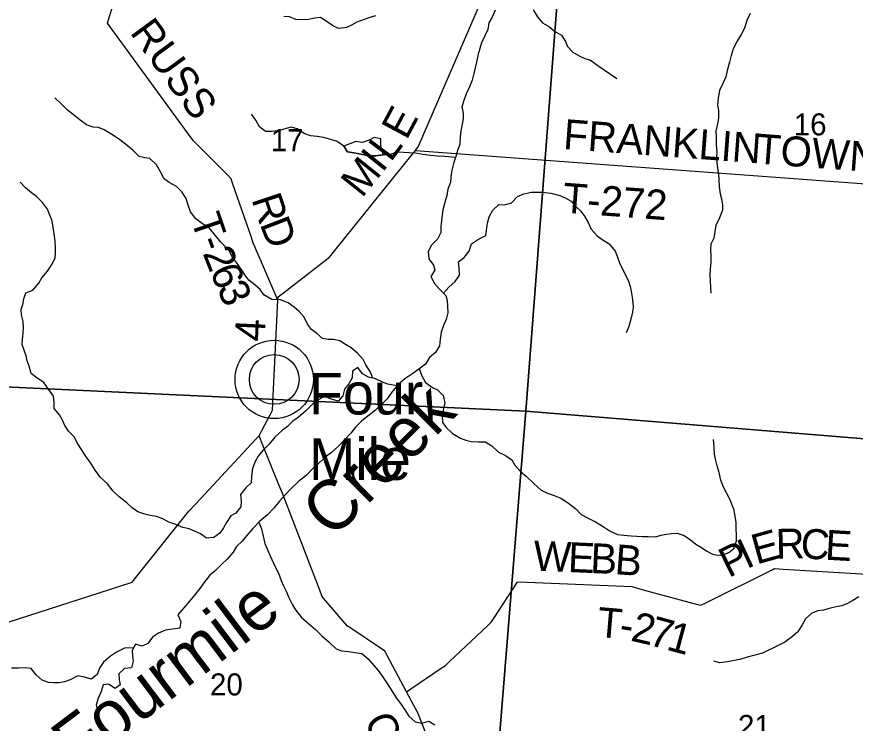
# Model space of a CAD drawing. Extents: x 0 to 42, y 0 to 22.
# Drawn here: x 2.716 to 3.512, y 17.925 to 18.596 of the extents above; entities that cross this region are included whole.
import ezdxf

# ---------------------------------------------------------------- set-up
doc = ezdxf.new("R2010")
doc.units = 0
for name, color, linetype in [('GM_X_County_Road', 7, 'Continuous'), ('GM_X_County_Road_Text', 7, 'Continuous'), ('GM_X_Minor_Lake', 7, 'Continuous'), ('GM_X_Minor_River', 7, 'Continuous'), ('GM_X_Minor_River_Text', 7, 'Continuous'), ('GM_X_Section', 7, 'Continuous'), ('GM_X_Section_Text', 7, 'Continuous'), ('GM_X_Township_Road', 7, 'Continuous'), ('GM_X_Township_Road_Text', 7, 'Continuous'), ('GM_X_Unincorporated', 7, 'Continuous'), ('GM_X_Unincorporated_Location', 7, 'Continuous'), ('GM_X_Unincorporated_Text', 7, 'Continuous')]:
    doc.layers.add(name, color=color, linetype=linetype)

msp = doc.modelspace()

# ---------------------------------------------------------------- linework, layer by layer
at = {"layer": 'GM_X_County_Road'}
for points in [[(2.94626, 18.1983), (2.94861, 18.20278), (2.95764, 18.22006), (2.95897, 18.22261), (2.95931, 18.22947), (2.96412, 18.32681), (2.96428, 18.3301), (2.96939, 18.33404), (3.01182, 18.36678), (3.01303, 18.3677), (3.01819, 18.3741), (3.09159, 18.46515), (3.09478, 18.46912), (3.0976, 18.47306), (3.21925, 18.75503)], [(2.48506, 17.97141), (2.49188, 17.97404), (2.50643, 17.97938), (2.51843, 17.98366), (2.54665, 17.99534), (2.55686, 17.99531), (2.63519, 17.99232), (2.6369, 17.99225), (2.6435, 17.99691), (2.6515, 18.00257), (2.65302, 18.00364), (2.66057, 18.00607), (2.67923, 18.01208), (2.8238, 18.05864), (2.82582, 18.05928), (2.83058, 18.06526), (2.87941, 18.12659), (2.88608, 18.13376), (2.94289, 18.19468), (2.94626, 18.1983)], [(3.11725, 17.88388), (3.09745, 17.93368), (3.0963, 17.93658), (3.09317, 17.94242), (3.08627, 17.95531), (3.06787, 17.98968), (3.06557, 17.99394), (3.06151, 17.99668), (3.03322, 18.01571), (3.03029, 18.01768), (3.0262, 18.02237), (3.00697, 18.0444), (3.00658, 18.04484), (3.00328, 18.05338), (2.96813, 18.14428), (2.96446, 18.1533), (2.94985, 18.18944), (2.94626, 18.1983)]]:
    msp.add_lwpolyline(points, dxfattribs=at)
at = {"layer": 'GM_X_Minor_Lake'}
for points in [[(3.06396, 18.46475), (3.06191, 18.47385), (3.06174, 18.47992), (3.05551, 18.48146), (3.05058, 18.47864), (3.04452, 18.47658), (3.03809, 18.47755), (3.02673, 18.47323)], [(3.02673, 18.47323), (3.03011, 18.46772), (3.03616, 18.46675), (3.04315, 18.46559), (3.04996, 18.46405), (3.05715, 18.46402), (3.06396, 18.46475)]]:
    msp.add_lwpolyline(points, dxfattribs=at)
at = {"layer": 'GM_X_Minor_River'}
for points in [[(3.17039, 18.60213), (3.16753, 18.59551), (3.16448, 18.59003), (3.16332, 18.58378), (3.16046, 18.57772), (3.15741, 18.5711), (3.15569, 18.5658), (3.15416, 18.56031), (3.15262, 18.55292), (3.15146, 18.54743), (3.15012, 18.54213), (3.14839, 18.53588), (3.14591, 18.52926), (3.14286, 18.52263), (3.14057, 18.51658), (3.13884, 18.51052), (3.13995, 18.50426), (3.13994, 18.49933), (3.13897, 18.49403), (3.13762, 18.48778), (3.13722, 18.4821), (3.13682, 18.47508), (3.13453, 18.46884), (3.13299, 18.46316), (3.1307, 18.45672), (3.12916, 18.45047), (3.12838, 18.44403), (3.1278, 18.43873), (3.1255, 18.43229), (3.12453, 18.42623), (3.12262, 18.41979), (3.1207, 18.41279), (3.12012, 18.40805), (3.11953, 18.40218), (3.11875, 18.39725), (3.11873, 18.39119), (3.11549, 18.38495), (3.1096, 18.3789), (3.10675, 18.37285), (3.10748, 18.36621), (3.11181, 18.36032), (3.11311, 18.35558), (3.10931, 18.34934), (3.11269, 18.34269), (3.11759, 18.33736), (3.12343, 18.33147), (3.12492, 18.32653), (3.12509, 18.32123), (3.12526, 18.31478), (3.12391, 18.30853), (3.12124, 18.30286), (3.11914, 18.29661), (3.11798, 18.28998), (3.11739, 18.28373), (3.11377, 18.2773), (3.10789, 18.27239), (3.10408, 18.26615), (3.09782, 18.26163), (3.09213, 18.25748)], [(3.20633, 18.60237), (3.21047, 18.59572), (3.21518, 18.59002), (3.22178, 18.5862), (3.22668, 18.58221), (3.23329, 18.57839), (3.23705, 18.57231), (3.23893, 18.56756), (3.24401, 18.56224), (3.25062, 18.55842), (3.25553, 18.55632), (3.26082, 18.55478), (3.2678, 18.54964), (3.28591, 18.53744)], [(3.05669, 18.59688), (3.05139, 18.5952), (3.04609, 18.59332), (3.03908, 18.5907), (3.03396, 18.58787), (3.02922, 18.58562), (3.02203, 18.5847), (3.01674, 18.58699), (3.0109, 18.59118), (3.00467, 18.59519), (2.99918, 18.59464), (2.99312, 18.59334), (2.98783, 18.59298), (2.98121, 18.59338), (2.97497, 18.59587), (2.96987, 18.59608)], [(3.4123, 18.59912), (3.40925, 18.59231), (3.40696, 18.58512), (3.40391, 18.57906), (3.39991, 18.57263), (3.39629, 18.56544), (3.39438, 18.55901), (3.39284, 18.55295), (3.39054, 18.54481), (3.38919, 18.53894), (3.38652, 18.53269), (3.38328, 18.52588), (3.38193, 18.51887), (3.38153, 18.51205), (3.38227, 18.50693), (3.38224, 18.49973), (3.38127, 18.49424), (3.37993, 18.48723), (3.38009, 18.48192), (3.38026, 18.47434), (3.38061, 18.46751), (3.3804, 18.4624), (3.38076, 18.45766), (3.3815, 18.45235), (3.38223, 18.44609), (3.38259, 18.44135), (3.38294, 18.43453), (3.38406, 18.42789), (3.38517, 18.42314), (3.3861, 18.41708), (3.38608, 18.41234), (3.38321, 18.40496), (3.37997, 18.39777), (3.37882, 18.39171), (3.37804, 18.38583), (3.37518, 18.37997), (3.37478, 18.37523), (3.37514, 18.36822), (3.37512, 18.36348), (3.37452, 18.35647), (3.37413, 18.35135), (3.37429, 18.3451), (3.37465, 18.33941), (3.3752, 18.33353)], [(3.05412, 18.25298), (3.05204, 18.25877), (3.04752, 18.26561), (3.04489, 18.27074), (3.03962, 18.27663), (3.03377, 18.28177), (3.0283, 18.28502), (3.02302, 18.28845), (3.01697, 18.28961), (3.01167, 18.28963), (3.00657, 18.2906), (3.00091, 18.29517), (2.99601, 18.29917), (2.99224, 18.30411), (2.98905, 18.31075), (2.98434, 18.31627), (2.97944, 18.32046), (2.97378, 18.32446), (2.96642, 18.32714), (2.95828, 18.32774), (2.95073, 18.33213), (2.94716, 18.33707), (2.94226, 18.34164), (2.93641, 18.34602), (2.93283, 18.35096), (2.92907, 18.35647), (2.92493, 18.36274), (2.92098, 18.36788), (2.91741, 18.37433), (2.91006, 18.38194), (2.90441, 18.3886), (2.89876, 18.39544), (2.89253, 18.39945), (2.88631, 18.40402), (2.88104, 18.41087), (2.87861, 18.41808), (2.87692, 18.42358), (2.87298, 18.42985), (2.8677, 18.4348), (2.8609, 18.43862), (2.856, 18.44205), (2.85262, 18.44888), (2.84886, 18.45534), (2.84264, 18.46143), (2.83772, 18.46202), (2.83243, 18.46317), (2.82659, 18.46888), (2.82093, 18.47383), (2.81414, 18.47917), (2.80886, 18.4826), (2.80395, 18.48565), (2.79905, 18.48851), (2.79376, 18.4908), (2.78884, 18.4912), (2.78242, 18.49331), (2.77638, 18.49788), (2.76959, 18.50322), (2.76431, 18.50741), (2.75828, 18.51331), (2.75225, 18.51883)], [(3.13274, 18.46245), (3.1224, 18.4632), (3.11559, 18.4636), (3.10898, 18.46439), (3.1016, 18.46517), (3.09461, 18.46634), (3.08837, 18.46674), (3.08345, 18.46695), (3.07683, 18.46735), (3.07001, 18.46473), (3.06396, 18.46475), (3.05715, 18.46402), (3.04996, 18.46405), (3.04315, 18.46559), (3.03616, 18.46675), (3.03011, 18.46772), (3.02673, 18.47323), (3.0205, 18.47762), (3.01351, 18.47973), (3.00746, 18.48127), (3.00123, 18.48224), (2.99517, 18.48283), (2.9897, 18.48475), (2.98253, 18.4897), (2.97686, 18.49105), (2.97193, 18.48993), (2.96569, 18.48806), (2.95868, 18.48695), (2.95225, 18.48716), (2.94678, 18.49135), (2.94302, 18.49781), (2.93907, 18.50351)], [(2.74955, 18.40322), (2.7473, 18.40835), (2.74543, 18.41328), (2.74072, 18.41974), (2.73507, 18.42526), (2.73016, 18.42869), (2.72451, 18.43364), (2.71942, 18.43878)], [(3.12135, 18.33356), (3.12648, 18.33942), (3.13237, 18.34451), (3.13636, 18.35056), (3.13619, 18.35719), (3.13565, 18.36345), (3.14077, 18.36741), (3.14571, 18.37346), (3.14801, 18.38046), (3.15446, 18.38499), (3.16147, 18.38837), (3.16224, 18.39311), (3.16302, 18.39993), (3.16456, 18.40599), (3.16818, 18.41242), (3.17387, 18.41789), (3.17917, 18.4173), (3.18579, 18.41917), (3.19149, 18.42522), (3.19755, 18.42785), (3.20475, 18.42952), (3.20966, 18.42932), (3.21477, 18.4293), (3.22328, 18.42851), (3.23178, 18.42639), (3.23669, 18.42391), (3.24236, 18.42085), (3.24669, 18.4161), (3.25159, 18.41134), (3.25517, 18.40659), (3.25855, 18.4007), (3.26155, 18.39424), (3.26701, 18.38797), (3.27192, 18.38454), (3.27871, 18.38034), (3.28417, 18.3735), (3.28605, 18.36875), (3.28848, 18.3623), (3.29167, 18.35565), (3.29411, 18.3509), (3.29693, 18.34483), (3.29861, 18.33989), (3.29991, 18.33344), (3.30084, 18.32737), (3.30119, 18.32055), (3.30079, 18.31562), (3.29925, 18.30881), (3.29715, 18.30199), (3.29467, 18.29594)], [(3.07713, 18.24575), (3.06845, 18.24715), (3.06354, 18.24906), (3.05674, 18.25231), (3.04994, 18.25404), (3.04428, 18.2569), (3.03995, 18.26299), (3.03502, 18.25959), (3.03461, 18.25315), (3.03138, 18.24767), (3.02739, 18.24237), (3.02566, 18.23613), (3.02129, 18.23122), (3.01487, 18.23295), (3.00845, 18.23544), (3.00219, 18.23224), (2.9965, 18.2279), (2.99024, 18.22148), (2.98322, 18.21563), (2.97828, 18.21205), (2.97335, 18.20714), (2.96823, 18.20318), (2.96121, 18.19695), (2.95588, 18.19015), (2.94981, 18.1843), (2.94544, 18.17882), (2.94239, 18.1739), (2.93991, 18.16728), (2.93913, 18.15989), (2.93873, 18.15363), (2.9336, 18.14873), (2.92866, 18.14268), (2.9292, 18.13623), (2.92881, 18.13093), (2.92424, 18.12469), (2.91932, 18.12225), (2.91532, 18.11601), (2.91246, 18.1109), (2.90904, 18.10598), (2.90316, 18.10184), (2.89616, 18.10111), (2.8905, 18.10511), (2.88484, 18.10778), (2.87974, 18.11008), (2.87388, 18.11124), (2.86727, 18.11392), (2.86047, 18.11622), (2.8548, 18.11946), (2.84895, 18.12157), (2.8429, 18.12273), (2.8378, 18.12389), (2.83119, 18.12618), (2.82571, 18.13), (2.82081, 18.13456), (2.81327, 18.14028), (2.80761, 18.1458), (2.80234, 18.15264), (2.79556, 18.15854), (2.79047, 18.16557), (2.78577, 18.17317), (2.7822, 18.17831), (2.7775, 18.18534), (2.7743, 18.19066), (2.77054, 18.19711), (2.76527, 18.20263), (2.76188, 18.20814), (2.75963, 18.21308), (2.75662, 18.21802), (2.75173, 18.2241), (2.75156, 18.22979), (2.7512, 18.23585), (2.74631, 18.24251), (2.74198, 18.24897), (2.73556, 18.25278), (2.72972, 18.25735), (2.72785, 18.26437), (2.72617, 18.2695), (2.72524, 18.27424), (2.72337, 18.27936), (2.72131, 18.28449), (2.72151, 18.28961), (2.72229, 18.29548), (2.72269, 18.30059), (2.72214, 18.30666), (2.72066, 18.31311), (2.72048, 18.31804), (2.72202, 18.32296), (2.72298, 18.32827), (2.7247, 18.33394), (2.73133, 18.33657), (2.73722, 18.34318), (2.74008, 18.3481), (2.7454, 18.35452), (2.75015, 18.3619), (2.75263, 18.3672), (2.75303, 18.37193), (2.75305, 18.37667), (2.75269, 18.38293), (2.75195, 18.38767), (2.75048, 18.39829), (2.74955, 18.40322)], [(3.09833, 18.26199), (3.10064, 18.25517), (3.10421, 18.24871), (3.11081, 18.24395), (3.11572, 18.24185), (3.121, 18.23633), (3.12248, 18.2295), (3.12094, 18.22249), (3.12017, 18.21738), (3.12033, 18.21093), (3.12372, 18.20618), (3.12994, 18.20047), (3.1373, 18.1959), (3.1424, 18.19398), (3.14769, 18.19282), (3.15412, 18.19242), (3.16075, 18.19258), (3.16716, 18.18877), (3.17338, 18.18268), (3.17999, 18.17962), (3.18603, 18.17543), (3.18903, 18.17049), (3.1945, 18.16421), (3.19978, 18.15983), (3.20751, 18.1526), (3.2141, 18.14651), (3.22015, 18.14383), (3.22619, 18.14154), (3.2328, 18.13905), (3.23997, 18.13428), (3.24676, 18.12895), (3.25185, 18.12362), (3.25751, 18.12057), (3.26563, 18.11656), (3.2728, 18.11217), (3.27941, 18.1076), (3.28658, 18.10473), (3.29263, 18.10394), (3.29944, 18.10316), (3.30474, 18.10295), (3.30984, 18.10274), (3.31552, 18.10253), (3.32289, 18.10231), (3.32763, 18.104), (3.33293, 18.10493), (3.33785, 18.10548), (3.34296, 18.10583), (3.34976, 18.10353), (3.35579, 18.09953), (3.36089, 18.09553), (3.36617, 18.0921), (3.37126, 18.08867), (3.37655, 18.08599), (3.38147, 18.08503), (3.38657, 18.0852), (3.39226, 18.08745), (3.397, 18.09141), (3.39948, 18.09842), (3.39931, 18.10315), (3.39915, 18.1113), (3.39898, 18.11642), (3.39825, 18.12173), (3.39732, 18.1278), (3.39395, 18.13578), (3.39151, 18.14128), (3.38869, 18.14622), (3.38644, 18.15116), (3.38457, 18.15628), (3.38289, 18.1633), (3.38121, 18.16975), (3.37953, 18.17601), (3.3786, 18.18094), (3.37825, 18.18739), (3.37752, 18.19459)], [(3.09213, 18.25748), (3.08474, 18.25239), (3.07791, 18.24673), (3.0724, 18.23974), (3.06783, 18.23331), (3.06176, 18.22727), (3.05663, 18.22255), (3.04961, 18.21689), (3.04373, 18.21255), (3.03785, 18.20651), (3.03329, 18.20065), (3.02759, 18.1948), (3.02208, 18.18857), (3.01506, 18.18234), (3.01032, 18.17876), (3.0033, 18.17272), (2.99722, 18.16706), (2.99077, 18.16064), (2.98356, 18.15479), (2.97673, 18.14837), (2.97084, 18.14233), (2.96552, 18.13609), (2.9602, 18.12948), (2.95412, 18.12325), (2.94691, 18.11721), (2.94027, 18.11022), (2.93438, 18.10323), (2.93001, 18.09832), (2.92488, 18.09323), (2.92165, 18.08793), (2.91595, 18.08132), (2.91063, 18.07622), (2.90456, 18.06999), (2.89963, 18.06584), (2.89374, 18.05885), (2.89012, 18.05337), (2.88499, 18.04694), (2.88024, 18.04127), (2.87492, 18.03485), (2.86922, 18.02843), (2.87204, 18.02197), (2.87107, 18.01572), (2.86388, 18.0148), (2.85725, 18.01369), (2.85081, 18.01087), (2.84493, 18.0071), (2.84056, 18.00125), (2.83525, 17.99861), (2.82902, 18.00053), (2.82578, 17.99448), (2.82595, 17.98898), (2.82669, 17.98424), (2.82515, 17.97818), (2.81834, 17.97726), (2.81303, 17.97235), (2.81338, 17.96666), (2.8145, 17.96192), (2.80976, 17.95834), (2.80315, 17.96253), (2.79823, 17.96198), (2.79632, 17.95555), (2.79308, 17.94817), (2.79173, 17.94249), (2.79322, 17.93623), (2.79376, 17.9277), (2.79431, 17.92277)], [(2.94595, 18.1162), (2.9484, 18.10981), (2.95008, 18.10298), (2.95175, 18.09596), (2.95438, 18.08951), (2.95663, 18.08438), (2.96001, 18.07736), (2.96226, 18.07261), (2.9647, 18.06786), (2.96732, 18.06084), (2.96939, 18.05591), (2.97183, 18.05078), (2.97445, 18.0447), (2.97783, 18.03787), (2.98084, 18.03312), (2.98649, 18.02589), (2.99309, 18.01999), (2.99969, 18.01447), (3.00591, 18.00857), (3.01288, 18.00229), (3.01948, 17.9962), (3.02439, 17.99428), (3.03101, 17.9935), (3.03725, 17.99272), (3.04367, 17.99156), (3.0499, 17.98661), (3.05517, 17.98014), (3.05931, 17.97539), (3.06402, 17.96892), (3.06778, 17.96303), (3.07229, 17.95619), (3.07624, 17.94973), (3.08151, 17.94289), (3.08452, 17.93814), (3.08828, 17.93206), (3.0945, 17.92673), (3.10074, 17.92557), (3.10737, 17.92744), (3.11303, 17.92401)], [(3.51555, 18.04546), (3.50987, 18.04188), (3.50494, 18.03906), (3.49945, 18.037), (3.49416, 18.03589), (3.48753, 18.0344), (3.48205, 18.03272), (3.47656, 18.03199), (3.47089, 18.02993), (3.46482, 18.02446), (3.46177, 18.01898), (3.45777, 18.01217)], [(3.45777, 18.01217), (3.45246, 18.00764), (3.44544, 18.00256), (3.43901, 17.99918), (3.42412, 17.992)], [(2.82719, 17.99711), (2.81841, 17.99678), (2.81083, 17.99283), (2.80533, 17.98906), (2.7985, 17.9834), (2.79508, 17.97849), (2.79241, 17.97186), (2.78671, 17.96715), (2.78048, 17.96925), (2.77405, 17.97061), (2.76685, 17.96665), (2.76136, 17.96478), (2.75644, 17.96366), (2.75133, 17.96387), (2.74641, 17.96427), (2.74037, 17.96638), (2.73471, 17.97151), (2.72982, 17.97741), (2.72434, 17.97819), (2.71771, 17.97765), (2.71109, 17.97767)], [(3.42412, 17.992), (3.41686, 17.98994), (3.40948, 17.98826), (3.40247, 17.98582), (3.39717, 17.98489), (3.39074, 17.98378), (3.38373, 17.98267), (3.37788, 17.9844)]]:
    msp.add_lwpolyline(points, dxfattribs=at)
at = {"layer": 'GM_X_Section'}
for points in [[(2.6719, 18.75482), (2.70486, 18.75248), (3.20711, 18.71245), (3.23685, 18.70974), (3.1993, 18.2215), (2.65705, 18.24703), (2.65641, 18.49422)], [(3.23685, 18.70974), (3.7313, 18.67044), (3.68779, 18.18177), (3.1993, 18.2215)], [(2.65705, 18.24703), (3.1993, 18.2215), (3.15501, 17.67437), (2.6558, 17.7233)], [(3.68779, 18.18177), (3.62739, 17.63591), (3.15501, 17.67437), (3.1993, 18.2215)]]:
    msp.add_lwpolyline(points, close=True, dxfattribs=at)
at = {"layer": 'GM_X_Township_Road'}
for points in [[(2.96412, 18.32681), (2.96216, 18.33138), (2.94254, 18.37707), (2.94076, 18.38119), (2.93898, 18.38634), (2.92113, 18.43805), (2.91971, 18.44216), (2.91578, 18.44613), (2.88433, 18.47796), (2.88367, 18.47862), (2.87835, 18.4859), (2.805, 18.58624), (2.8023, 18.58992), (2.80392, 18.59505), (2.81293, 18.6235)], [(3.09478, 18.46912), (3.71461, 18.42296), (3.75827, 18.47688)], [(3.08627, 17.95531), (3.09039, 17.9581), (3.11921, 17.97766), (3.12304, 17.98026), (3.12691, 17.9839), (3.16316, 18.01799), (3.16667, 18.02128), (3.16946, 18.02559), (3.19111, 18.05901), (3.19152, 18.05965), (3.2007, 18.05926), (3.30012, 18.05509), (3.30972, 18.05251), (3.36255, 18.03821), (3.36545, 18.03742), (3.37167, 18.04051), (3.43406, 18.07149), (3.43544, 18.07217), (3.44384, 18.07167), (3.67727, 18.05786)]]:
    msp.add_lwpolyline(points, dxfattribs=at)
at = {"layer": 'GM_X_Unincorporated'}
for radius in [0.0372, 0.02358]:
    msp.add_circle((2.96058, 18.2517), radius, dxfattribs=at)
at = {"layer": 'GM_X_Unincorporated_Location'}
msp.add_line((2.96058, 18.2517), (2.96058, 18.2517), dxfattribs=at)

# ---------------------------------------------------------------- texts
at = {"layer": 'GM_X_County_Road_Text'}
for s, rotation, p in [('E', 61.87041, (3.08621, 18.47808)), ('L', 53.39023, (3.07112, 18.45721)), ('I', 51.3222, (3.06316, 18.44724)), ('M', 51.28853, (3.04386, 18.42316)), ('4', 87.27516, (2.9515, 18.28733)), ('C', 294.83157, (3.04537, 17.92783))]:
    msp.add_text(s, height=0.02841, rotation=rotation, dxfattribs=at).set_placement(p)
at = {"layer": 'GM_X_Minor_River_Text'}
for s, height, rotation, p in [('Creek', 0.04735, 45.00289, (3.01607, 18.09938)), ('Fourmile', 0.047349, 37.00209, (2.77284, 17.87994))]:
    msp.add_text(s, height=height, rotation=rotation, dxfattribs=at).set_placement(p)
at = {"layer": 'GM_X_Section_Text'}
for s, p in [('16', (3.45377, 18.4833)), ('17', (2.95731, 18.46835)), ('20', (2.8996, 17.95184)), ('21', (3.40085, 17.91242))]:
    msp.add_text(s, height=0.020928, rotation=0.00001, dxfattribs=at).set_placement(p)
at = {"layer": 'GM_X_Township_Road_Text'}
for s, height, rotation, p in [('RUSS', 0.028409, 306.20982, (2.823, 18.58092)), ('FRANKLIN', 0.028409, 355.77894, (3.23438, 18.47047)), ('TOWNHOUSE', 0.028409, 355.732, (3.41731, 18.45672)), ('T-272', 0.028409, 355.77416, (3.23367, 18.41014)), ('R', 0.02841, 288.39299, (2.93877, 18.42279)), ('T', 0.02841, 288.88898, (2.88102, 18.40393)), ('D', 0.02841, 291.08283, (2.94662, 18.3993)), ('2', 0.02841, 291.54034, (2.89244, 18.37154)), ('-', 0.02841, 290.29106, (2.88815, 18.38311)), ('6', 0.02841, 292.73662, (2.89911, 18.35466)), ('3', 0.02841, 293.13682, (2.90595, 18.33832)), ('E', 0.02841, 15.61633, (3.4184, 18.07596)), ('R', 0.02841, 1.49501, (3.43704, 18.08141)), ('C', 0.02841, 356.80177, (3.45975, 18.08203)), ('E', 0.02841, 356.77548, (3.48304, 18.08073)), ('I', 0.02841, 24.80185, (3.40894, 18.07149)), ('W', 0.02841, 357.47872, (3.20613, 18.07047)), ('E', 0.02841, 357.47489, (3.23902, 18.06902)), ('B', 0.02841, 357.44263, (3.26024, 18.06809)), ('B', 0.02841, 355.55011, (3.2833, 18.06706)), ('P', 0.02841, 26.29093, (3.39193, 18.06308)), ('T', 0.02841, 355.06512, (3.26647, 18.00749)), ('2', 0.02841, 346.91376, (3.29811, 18.004)), ('7', 0.02841, 344.87592, (3.3149, 18.0001)), ('1', 0.02841, 344.87592, (3.33179, 17.99553)), ('-', 0.02841, 350.98944, (3.28711, 18.00572))]:
    msp.add_text(s, height=height, rotation=rotation, dxfattribs=at).set_placement(p)
at = {"layer": 'GM_X_Unincorporated_Text'}
for s, p in [('Four', (2.99356, 18.21846)), ('Mile', (2.99356, 18.15637))]:
    msp.add_text(s, height=0.039489, rotation=0.00001, dxfattribs=at).set_placement(p)

doc.saveas('drawing.dxf')
